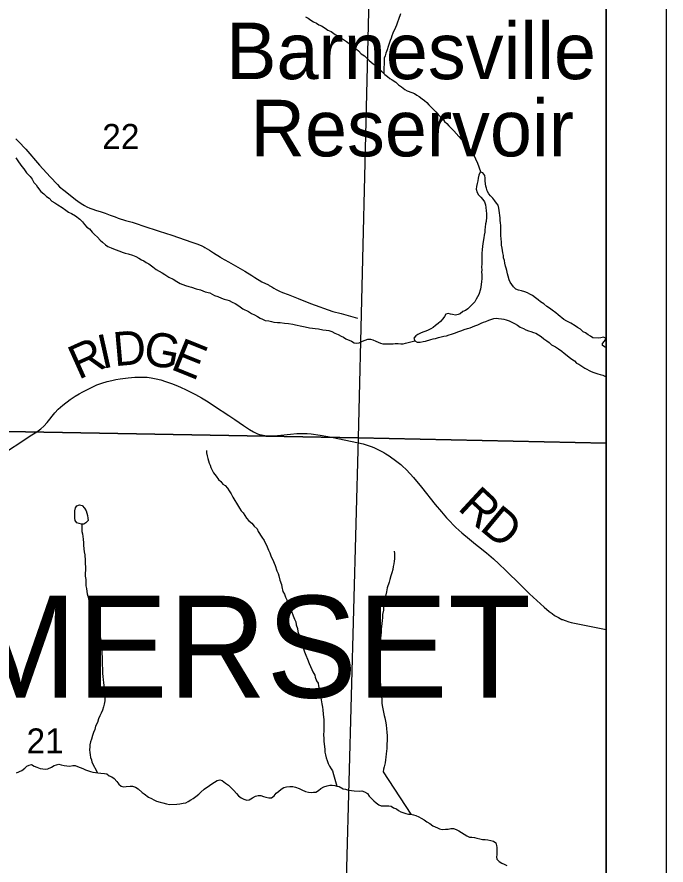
# Model space of a CAD drawing. Extents: x 0 to 34, y 0 to 22.
# Drawn here: x 29.33 to 30.417, y 16.803 to 18.224 of the extents above; entities that cross this region are included whole.
import ezdxf

# ---------------------------------------------------------------- set-up
doc = ezdxf.new("R2010")
doc.units = 0
for name, color, linetype in [('GM_X_Corporation', 7, 'Continuous'), ('GM_X_County_Road', 7, 'Continuous'), ('GM_X_County_Road_Text', 7, 'Continuous'), ('GM_X_Major_Lake', 7, 'Continuous'), ('GM_X_Major_Lake_Text', 7, 'Continuous'), ('GM_X_Minor_River', 7, 'Continuous'), ('GM_X_Section_Text', 7, 'Continuous'), ('GM_X_Township_Road', 7, 'Continuous'), ('GM_X_Township_Text', 7, 'Continuous'), ('SH_Data', 7, 'Continuous')]:
    doc.layers.add(name, color=color, linetype=linetype)

msp = doc.modelspace()

# ---------------------------------------------------------------- linework, layer by layer
at = {"layer": 'GM_X_Corporation'}
for points in [[(27.8031, 14.5091), (28.4032, 14.497), (28.7853, 14.4893), (29.1713, 14.4832), (29.2367, 14.4822), (30.3098, 14.464), (30.3167, 14.4639), (30.3167, 20.9), (27.1022, 20.9)], [(27.8031, 14.5091), (28.4032, 14.497), (28.7853, 14.4893), (29.1713, 14.4832), (29.2367, 14.4822), (30.3098, 14.464), (30.3167, 14.4639), (30.3167, 20.3649), (29.5503, 20.3788), (27.6751, 20.4106)]]:
    msp.add_lwpolyline(points, dxfattribs=at)
for points in [[(29.9261, 18.5329), (29.9011, 17.5188), (28.8799, 17.5369), (28.8973, 18.5532)], [(30.3167, 17.5099), (30.3167, 18.5238), (29.9261, 18.5329), (29.9011, 17.5188)], [(28.8799, 17.5369), (29.9011, 17.5188), (29.8741, 16.51), (28.863, 16.5324)], [(30.3167, 16.4991), (30.3167, 17.5099), (29.9011, 17.5188), (29.8741, 16.51)]]:
    msp.add_lwpolyline(points, close=True, dxfattribs=at)
at = {"layer": 'GM_X_County_Road'}
msp.add_lwpolyline([(29.3159, 17.4978), (29.3365, 17.5113), (29.3525, 17.522), (29.3634, 17.5289), (29.37, 17.5337), (29.3749, 17.538), (29.3805, 17.5445), (29.3934, 17.5604), (29.3991, 17.5669), (29.4071, 17.5736), (29.4192, 17.5826), (29.4259, 17.5871), (29.4276, 17.5883), (29.4341, 17.5922), (29.4406, 17.5959), (29.4449, 17.5981), (29.4573, 17.6041), (29.4641, 17.6072), (29.4724, 17.6103), (29.4814, 17.613), (29.4892, 17.6149), (29.4954, 17.6162), (29.5029, 17.6175), (29.5161, 17.6193), (29.5272, 17.6201), (29.5366, 17.6205), (29.5428, 17.6204), (29.5482, 17.6201), (29.555, 17.6194), (29.5633, 17.6177), (29.571, 17.6157), (29.5789, 17.6132), (29.5887, 17.6097), (29.5962, 17.6069), (29.6037, 17.6037), (29.6135, 17.5992), (29.6214, 17.5952), (29.6288, 17.5913), (29.6388, 17.5855), (29.6501, 17.5788), (29.6611, 17.5719), (29.6847, 17.5563), (29.695, 17.5492), (29.7093, 17.5393), (29.7194, 17.5326), (29.7263, 17.5285), (29.7294, 17.5271), (29.733, 17.5256), (29.7363, 17.5244), (29.7396, 17.5236), (29.7451, 17.5225), (29.7498, 17.522), (29.7547, 17.5219), (29.7602, 17.5221), (29.7664, 17.5226), (29.7879, 17.525), (29.7989, 17.5259), (29.8042, 17.526), (29.8159, 17.5257), (29.8229, 17.5252), (29.8375, 17.523), (29.8503, 17.5207), (29.8565, 17.5196), (29.8912, 17.5127), (29.9099, 17.5083), (29.9178, 17.5059), (29.9232, 17.504), (29.9276, 17.5022), (29.9351, 17.4988), (29.9442, 17.494), (29.9479, 17.4918), (29.9532, 17.4883), (29.9662, 17.4791), (29.9726, 17.4741), (29.9757, 17.4714), (29.9818, 17.4658), (29.9885, 17.4586), (29.9938, 17.4524), (30.0071, 17.4361), (30.0304, 17.4071), (30.0408, 17.3944), (30.0491, 17.3848), (30.0546, 17.3789), (30.0609, 17.3724), (30.0647, 17.3687), (30.0751, 17.3594), (30.0877, 17.3487), (30.0978, 17.3406), (30.1026, 17.3368), (30.116, 17.3259), (30.1279, 17.3157), (30.1368, 17.3077), (30.1486, 17.2965), (30.1733, 17.2722), (30.1883, 17.2572), (30.2126, 17.2351), (30.2211, 17.228), (30.2259, 17.2242), (30.2302, 17.2213), (30.2366, 17.2175), (30.2425, 17.2146), (30.2435, 17.2142), (30.2481, 17.2124), (30.2538, 17.2106), (30.2576, 17.2095), (30.2634, 17.2082), (30.3167, 17.1977)], dxfattribs=at)
at = {"layer": 'GM_X_Major_Lake'}
for points in [[(30.3167, 17.6695), (30.3147, 17.6706), (30.3101, 17.6731), (30.3104, 17.6769), (30.3138, 17.6808), (30.3164, 17.685), (30.3118, 17.6872), (30.3073, 17.686), (30.3035, 17.6855), (30.2944, 17.6861), (30.2902, 17.6887), (30.2864, 17.6909), (30.2817, 17.6946), (30.2779, 17.6964), (30.2733, 17.7005), (30.2687, 17.7035), (30.2645, 17.7064), (30.2572, 17.7109), (30.2504, 17.7142), (30.2458, 17.7171), (30.2362, 17.7245), (30.2324, 17.7279), (30.2258, 17.7323), (30.2216, 17.7356), (30.217, 17.7386), (30.212, 17.743), (30.2067, 17.7464), (30.2025, 17.7497), (30.1979, 17.7534), (30.1929, 17.7571), (30.1887, 17.7593), (30.1848, 17.7615), (30.1803, 17.763), (30.175, 17.7648), (30.1696, 17.7662), (30.1651, 17.7676), (30.1616, 17.7717), (30.1585, 17.7755), (30.1558, 17.7792), (30.1542, 17.7833), (30.1526, 17.7894), (30.1514, 17.7935), (30.1501, 17.7988), (30.1489, 17.8026), (30.1481, 17.8064), (30.1469, 17.8113), (30.1461, 17.8158), (30.1448, 17.8203), (30.1444, 17.8241), (30.1436, 17.8287), (30.1427, 17.8324), (30.1423, 17.8366), (30.1415, 17.8415), (30.141, 17.8464), (30.1405, 17.8521), (30.1404, 17.8574), (30.1399, 17.8631), (30.1399, 17.8677), (30.1401, 17.8745), (30.1397, 17.8786), (30.1392, 17.8824), (30.1388, 17.887), (30.1374, 17.8995), (30.1366, 17.9036), (30.1354, 17.9081), (30.133, 17.9119), (30.1303, 17.9156), (30.1265, 17.9201), (30.123, 17.9239), (30.1199, 17.9276), (30.1172, 17.9321), (30.116, 17.9366), (30.1148, 17.9404), (30.1143, 17.9442), (30.1138, 17.9491), (30.1138, 17.9536), (30.1133, 17.9582), (30.1098, 17.9627), (30.1053, 17.9634), (30.1035, 17.9588), (30.1024, 17.9538), (30.1017, 17.9493), (30.1007, 17.9447), (30.0996, 17.9397), (30.0989, 17.9352), (30.1006, 17.9295), (30.1029, 17.9254), (30.1067, 17.922), (30.1098, 17.9179), (30.1126, 17.9138)], [(30.1126, 17.9138), (30.1142, 17.9089), (30.115, 17.9044), (30.1155, 17.8991), (30.1159, 17.8945), (30.116, 17.8881), (30.1154, 17.8812), (30.1147, 17.8771), (30.1141, 17.8717), (30.1134, 17.8668), (30.1131, 17.863), (30.1124, 17.8581), (30.1117, 17.8535), (30.1107, 17.8474), (30.1097, 17.8398), (30.109, 17.8334), (30.1084, 17.8277), (30.1081, 17.8235), (30.1083, 17.8098), (30.108, 17.8045), (30.1081, 17.8), (30.1078, 17.7962), (30.1082, 17.7924), (30.1084, 17.7848), (30.1077, 17.7803), (30.1074, 17.7757), (30.1067, 17.7715), (30.106, 17.7677), (30.1032, 17.7586), (30.101, 17.7547), (30.0991, 17.7509), (30.0966, 17.7467), (30.0932, 17.7428), (30.0895, 17.739), (30.085, 17.7347), (30.0809, 17.732), (30.0768, 17.73), (30.0723, 17.7265), (30.0686, 17.725), (30.064, 17.7241), (30.0595, 17.7252), (30.0557, 17.7259), (30.0519, 17.7269), (30.0481, 17.7257), (30.0459, 17.7219), (30.0433, 17.7181), (30.0392, 17.7134), (30.0351, 17.7103), (30.0307, 17.7068), (30.0266, 17.7034), (30.0228, 17.701), (30.0183, 17.6987), (30.0146, 17.6971), (30.0097, 17.6955), (30.0059, 17.6939), (30.0014, 17.6919), (29.9977, 17.6896), (29.9947, 17.6857), (29.9959, 17.6812), (30.0001, 17.679), (30.005, 17.6787), (30.0099, 17.6799), (30.0141, 17.6808), (30.0227, 17.6836), (30.0269, 17.6844), (30.0307, 17.6852), (30.0359, 17.6865), (30.0401, 17.6877), (30.0446, 17.6889), (30.0491, 17.6897), (30.0536, 17.6913), (30.0578, 17.6925), (30.0623, 17.6941), (30.0698, 17.6965), (30.0747, 17.6985), (30.0788, 17.7001), (30.0841, 17.7017), (30.089, 17.7029), (30.0965, 17.7061), (30.1014, 17.7081), (30.107, 17.7109), (30.1112, 17.7124), (30.1149, 17.7136), (30.1198, 17.7156), (30.1285, 17.7184), (30.1322, 17.7189), (30.1364, 17.7186), (30.141, 17.7179), (30.1451, 17.7176), (30.1493, 17.7165), (30.1543, 17.7147), (30.1585, 17.7125), (30.163, 17.7103), (30.168, 17.7074), (30.1726, 17.7041), (30.1779, 17.7015), (30.1818, 17.6993), (30.1863, 17.6979), (30.1901, 17.6968), (30.1947, 17.6953), (30.1985, 17.6939)], [(30.1985, 17.6939), (30.2031, 17.6913), (30.2077, 17.6884), (30.2123, 17.6847), (30.2173, 17.681), (30.2211, 17.6784), (30.225, 17.6746), (30.2315, 17.671), (30.2364, 17.6676), (30.2422, 17.6636), (30.2464, 17.6602), (30.251, 17.6565), (30.2548, 17.6539), (30.2591, 17.6506), (30.2633, 17.6477), (30.2667, 17.6439), (30.2706, 17.6421), (30.2809, 17.6354), (30.2916, 17.63), (30.2958, 17.6281), (30.3026, 17.626), (30.3064, 17.6249), (30.311, 17.6235), (30.3152, 17.6213), (30.3167, 17.6201)]]:
    msp.add_lwpolyline(points, dxfattribs=at)
at = {"layer": 'GM_X_Minor_River'}
for points in [[(29.9724, 18.2287), (29.9687, 18.2196), (29.9673, 18.2146), (29.9655, 18.21), (29.9637, 18.2058), (29.9593, 18.1966), (29.9575, 18.1921), (29.9564, 18.1882), (29.955, 18.1844), (29.9539, 18.1806), (29.9517, 18.1741), (29.9499, 18.1684), (29.9478, 18.1631), (29.9467, 18.1585), (29.9449, 18.1543), (29.9444, 18.129)], [(29.8131, 18.224), (29.8177, 18.2214), (29.8223, 18.2185), (29.8265, 18.2155), (29.8315, 18.2133), (29.8353, 18.2104), (29.8399, 18.2086), (29.846, 18.2049), (29.8506, 18.2012), (29.8559, 18.199), (29.8628, 18.1942), (29.8701, 18.1901), (29.8766, 18.1861), (29.8816, 18.1824), (29.8923, 18.1746), (29.8965, 18.1716), (29.9019, 18.1668), (29.9062, 18.1619), (29.9119, 18.1583), (29.9161, 18.1545), (29.92, 18.1508), (29.9265, 18.1449), (29.9315, 18.1404), (29.9365, 18.1359), (29.9407, 18.1322), (29.9461, 18.1274), (29.9507, 18.1241), (29.9546, 18.1207), (29.9584, 18.1181), (29.9641, 18.1141), (29.9688, 18.11), (29.9741, 18.1063), (29.9795, 18.1022), (29.9833, 18.1), (29.9909, 18.0971), (29.9955, 18.0953), (29.9997, 18.0927), (30.0035, 18.0901), (30.0085, 18.0864), (30.0124, 18.0834), (30.0162, 18.0801), (30.0197, 18.0764), (30.0235, 18.0726), (30.0278, 18.0678), (30.0316, 18.0648), (30.0351, 18.0603), (30.0386, 18.0566), (30.0428, 18.0529), (30.0459, 18.0484), (30.0497, 18.045), (30.0532, 18.0413), (30.0571, 18.0376), (30.0613, 18.0331), (30.0698, 18.0234), (30.074, 18.0189), (30.079, 18.0133), (30.0825, 18.0085), (30.0864, 18.0043), (30.0895, 18.0002), (30.0926, 17.9957), (30.0949, 17.9916), (30.0969, 17.9879), (30.0981, 17.9841), (30.1004, 17.9803), (30.1067, 17.9631)], [(29.328, 17.9874), (29.333, 17.9811), (29.3385, 17.9732), (29.3419, 17.9691), (29.3462, 17.9624), (29.352, 17.9564), (29.3555, 17.9519), (29.3586, 17.9463), (29.3621, 17.9422), (29.3648, 17.9384), (29.3702, 17.9313), (29.3752, 17.9276), (29.3795, 17.9231), (29.384, 17.9202), (29.3887, 17.9153), (29.3936, 17.9124), (29.3986, 17.9091), (29.4059, 17.9043), (29.412, 17.8998), (29.4166, 17.8969), (29.4216, 17.8943), (29.4281, 17.8906), (29.4354, 17.8847), (29.44, 17.8806), (29.4431, 17.8761), (29.4469, 17.8716), (29.4515, 17.8687), (29.4562, 17.8634), (29.46, 17.859), (29.465, 17.8545), (29.4696, 17.85), (29.4731, 17.8463), (29.4781, 17.8418), (29.4823, 17.8389), (29.4877, 17.8367), (29.4945, 17.8342), (29.5021, 17.8313), (29.506, 17.8294), (29.5113, 17.828), (29.5162, 17.827), (29.5238, 17.8248), (29.5292, 17.8223), (29.5341, 17.8197), (29.5387, 17.8168), (29.5425, 17.8149), (29.5467, 17.8124), (29.5509, 17.8102), (29.5575, 17.805), (29.5632, 17.8005), (29.5682, 17.798), (29.5732, 17.795), (29.5777, 17.7924), (29.5842, 17.788), (29.5915, 17.7843)], [(29.5915, 17.7843), (29.598, 17.7803), (29.6034, 17.7773), (29.6125, 17.7737), (29.6178, 17.7723), (29.6224, 17.7712), (29.6304, 17.7683), (29.6372, 17.7666), (29.6452, 17.7629), (29.6528, 17.7615), (29.6608, 17.7571), (29.6665, 17.7553), (29.6726, 17.7528), (29.6768, 17.751), (29.6814, 17.7495), (29.6852, 17.7485), (29.6906, 17.7459), (29.6955, 17.7437), (29.7016, 17.74), (29.7082, 17.7348), (29.7177, 17.7305), (29.7227, 17.7271), (29.7276, 17.7246), (29.733, 17.7216), (29.7372, 17.7191), (29.741, 17.7172), (29.7456, 17.7154), (29.7516, 17.7144), (29.7562, 17.7133), (29.76, 17.7126), (29.7661, 17.712), (29.771, 17.7117), (29.7782, 17.7107), (29.7846, 17.7101), (29.7918, 17.709), (29.7964, 17.708), (29.807, 17.7059), (29.8124, 17.7045), (29.8196, 17.7031), (29.8249, 17.7024), (29.8294, 17.7017), (29.8351, 17.7011), (29.8423, 17.6997), (29.8476, 17.699), (29.8522, 17.6984), (29.8571, 17.6969), (29.8625, 17.694), (29.8678, 17.6918), (29.8728, 17.6889), (29.8766, 17.687), (29.8808, 17.6845), (29.89, 17.6805), (29.8946, 17.6779), (29.8987, 17.6772), (29.9029, 17.6777), (29.9085, 17.6804), (29.913, 17.6824), (29.9175, 17.684), (29.9221, 17.6841), (29.9259, 17.683), (29.9308, 17.6808), (29.9347, 17.6786), (29.9388, 17.6772), (29.9426, 17.6761), (29.9464, 17.6758), (29.9502, 17.6762), (29.9555, 17.6763), (29.9597, 17.676), (29.9634, 17.6765), (29.968, 17.6765), (29.9729, 17.6762), (29.9767, 17.6763), (29.9805, 17.6771), (29.9959, 17.6812)], [(29.6472, 17.4975), (29.6477, 17.4934), (29.6485, 17.4885), (29.6497, 17.4839), (29.6509, 17.4802), (29.6517, 17.4764), (29.6533, 17.4726), (29.6545, 17.4689), (29.6592, 17.4598), (29.6635, 17.4542), (29.6677, 17.449), (29.6716, 17.4457), (29.675, 17.4412), (29.6789, 17.4386), (29.6827, 17.4345), (29.6855, 17.4296), (29.6886, 17.4247), (29.6917, 17.4195), (29.6948, 17.4135), (29.6979, 17.409), (29.7026, 17.4007), (29.7057, 17.3966), (29.7088, 17.3929), (29.7115, 17.3884), (29.7143, 17.3842), (29.7181, 17.3798), (29.7231, 17.3757), (29.7274, 17.3708), (29.732, 17.366), (29.7339, 17.3615), (29.7398, 17.3521), (29.744, 17.3469), (29.7491, 17.3363), (29.7511, 17.3307), (29.7535, 17.3262), (29.7559, 17.3194), (29.7586, 17.3141), (29.7606, 17.3085), (29.7626, 17.3047), (29.7654, 17.2957), (29.7673, 17.2915), (29.7685, 17.2874), (29.7702, 17.2802), (29.7729, 17.2731), (29.7734, 17.2693), (29.7754, 17.261), (29.7778, 17.2565), (29.7798, 17.2516), (29.7821, 17.2471), (29.7841, 17.241), (29.7865, 17.2346), (29.79, 17.2283), (29.7924, 17.2207), (29.7948, 17.2147), (29.7967, 17.2102), (29.7976, 17.2053), (29.7996, 17.1992), (29.8004, 17.1943), (29.8024, 17.1875), (29.8033, 17.1811), (29.8061, 17.1751), (29.8077, 17.1702), (29.81, 17.1653), (29.8116, 17.1604), (29.8136, 17.1548), (29.8164, 17.148), (29.8191, 17.1404), (29.8239, 17.1307), (29.8254, 17.1265), (29.8286, 17.1213), (29.8294, 17.1175), (29.8318, 17.1115), (29.8341, 17.1077), (29.8349, 17.1032), (29.8362, 17.0975), (29.8375, 17.0881), (29.8387, 17.0832), (29.8407, 17.073), (29.8416, 17.0677), (29.8421, 17.0631), (29.8429, 17.056), (29.8434, 17.0507), (29.8439, 17.0469), (29.844, 17.0393), (29.8441, 17.0336), (29.8438, 17.0272), (29.8435, 17.0218), (29.844, 17.0143), (29.8441, 17.0101), (29.8455, 16.9972), (29.8456, 16.9923), (29.8464, 16.9874), (29.848, 16.9825), (29.8492, 16.9783), (29.8512, 16.9731), (29.8535, 16.9686), (29.8559, 16.9644), (29.8582, 16.9607), (29.8598, 16.9547), (29.8658, 16.9354)], [(29.4382, 17.374), (29.4302, 17.3761), (29.4275, 17.3799), (29.4271, 17.384), (29.4269, 17.3928), (29.4272, 17.3965), (29.4283, 17.4011), (29.4305, 17.4049), (29.435, 17.4065), (29.4392, 17.4055), (29.443, 17.401), (29.4458, 17.3965), (29.4473, 17.3924), (29.4485, 17.3886), (29.449, 17.384), (29.4495, 17.3803), (29.4457, 17.376), (29.442, 17.3741), (29.4382, 17.374)], [(29.4386, 17.374), (29.4388, 17.3619), (29.4396, 17.3577), (29.4405, 17.3532), (29.4409, 17.349), (29.4414, 17.343), (29.4418, 17.3388), (29.4423, 17.3327), (29.4424, 17.3278), (29.4436, 17.3225), (29.4446, 17.3134), (29.4449, 17.2968), (29.4446, 17.2918), (29.4446, 17.2869), (29.4455, 17.2816), (29.4452, 17.2763), (29.4457, 17.271), (29.4465, 17.2665), (29.447, 17.2615), (29.4478, 17.2574), (29.449, 17.2536), (29.4498, 17.2491), (29.4514, 17.2446), (29.4539, 17.2348), (29.4551, 17.2302), (29.4563, 17.2261), (29.4575, 17.2212), (29.4595, 17.2155), (29.4615, 17.2106), (29.4627, 17.2065), (29.4647, 17.202), (29.467, 17.1967), (29.4682, 17.1918), (29.4687, 17.188), (29.4707, 17.1797), (29.4716, 17.1752), (29.4725, 17.1619), (29.4728, 17.1468), (29.4729, 17.1396), (29.4731, 17.1308), (29.4736, 17.1244), (29.4737, 17.1183), (29.4745, 17.1138), (29.475, 17.1085), (29.4754, 17.1043), (29.4763, 17.0975), (29.4772, 17.0919), (29.4773, 17.0831), (29.477, 17.0782), (29.4764, 17.0725), (29.4749, 17.0679), (29.4731, 17.0622), (29.471, 17.0573), (29.4688, 17.053), (29.4666, 17.0481), (29.4648, 17.0416), (29.4619, 17.0355), (29.4605, 17.0301), (29.4583, 17.0248), (29.4565, 17.0202), (29.4551, 17.0137), (29.4533, 17.0092), (29.4522, 17.0046), (29.4519, 17.0008), (29.4516, 16.9959), (29.452, 16.9917), (29.4525, 16.9879), (29.4533, 16.9834), (29.4549, 16.9792), (29.4557, 16.9755), (29.4648, 16.9576)], [(29.9616, 17.3288), (29.962, 17.325), (29.9622, 17.3159), (29.9618, 17.3121), (29.9612, 17.3075), (29.9601, 17.3029), (29.9591, 17.298), (29.9576, 17.2927), (29.9558, 17.2877), (29.9544, 17.2816), (29.953, 17.277), (29.9501, 17.2671), (29.9487, 17.2607), (29.947, 17.2534), (29.9459, 17.2492), (29.9456, 17.2454), (29.9446, 17.2401), (29.9439, 17.2356), (29.9436, 17.2302), (29.9422, 17.2226), (29.9419, 17.2169), (29.9413, 17.2124), (29.941, 17.2074), (29.9403, 17.2025), (29.94, 17.198), (29.9397, 17.1926), (29.939, 17.1885), (29.9387, 17.1824), (29.9381, 17.1771), (29.9378, 17.1725), (29.9375, 17.1668), (29.937, 17.1528), (29.9374, 17.1482), (29.9369, 17.1365), (29.9373, 17.1327), (29.9376, 17.1194), (29.938, 17.1149), (29.9381, 17.1107), (29.9386, 17.105), (29.9395, 17.096), (29.9399, 17.0922), (29.9404, 17.0865), (29.9409, 17.0793), (29.941, 17.0744), (29.9414, 17.0702), (29.9427, 17.0649), (29.9435, 17.0589), (29.9451, 17.0536), (29.946, 17.0498), (29.9476, 17.0415), (29.9481, 17.0374), (29.9489, 17.0317), (29.9494, 17.0249), (29.9499, 17.02), (29.95, 17.0135), (29.9494, 17.004), (29.9491, 16.998), (29.9485, 16.9938), (29.9482, 16.9892), (29.9479, 16.9839), (29.9472, 16.979), (29.9465, 16.9744), (29.9447, 16.9675), (29.9437, 16.9637), (29.943, 16.9592), (29.9893, 16.888)], [(29.3293, 16.9573), (29.3383, 16.9612), (29.3431, 16.9655), (29.3469, 16.9686), (29.3506, 16.9706), (29.3544, 16.9714), (29.359, 16.9688), (29.3632, 16.967), (29.3689, 16.9648), (29.3734, 16.9641), (29.378, 16.9638), (29.3821, 16.9643), (29.3878, 16.967), (29.3923, 16.9698), (29.3964, 16.971), (29.4005, 16.9718), (29.4043, 16.9711), (29.4093, 16.9697), (29.4135, 16.969), (29.4184, 16.9687), (29.4237, 16.9696), (29.4278, 16.9697), (29.4316, 16.9682), (29.4358, 16.9664), (29.4404, 16.9646), (29.445, 16.9624), (29.4534, 16.9595), (29.4572, 16.9588), (29.4617, 16.9581), (29.4655, 16.9574), (29.4704, 16.9572), (29.4769, 16.9565), (29.4807, 16.9558), (29.4845, 16.9525), (29.4891, 16.9507), (29.4929, 16.9481), (29.4972, 16.9428), (29.5006, 16.9387), (29.5045, 16.9354)], [(29.5045, 16.9354), (29.5087, 16.9343), (29.5128, 16.9344), (29.5196, 16.9349), (29.5238, 16.935), (29.5287, 16.9336), (29.5333, 16.9306), (29.5395, 16.9247), (29.5433, 16.9224), (29.5506, 16.9169), (29.5555, 16.9147), (29.5594, 16.9121), (29.5636, 16.9103), (29.5697, 16.9085), (29.5742, 16.9071), (29.5803, 16.9053), (29.5856, 16.9046), (29.5977, 16.9048), (29.6026, 16.9053), (29.6083, 16.9066), (29.6128, 16.9074), (29.6169, 16.9094), (29.621, 16.9121), (29.6252, 16.9144), (29.6297, 16.9176), (29.6345, 16.9218), (29.6382, 16.9249), (29.6438, 16.9299), (29.6524, 16.9362), (29.6561, 16.9393), (29.661, 16.9416), (29.6655, 16.9444), (29.6697, 16.9456), (29.6735, 16.9449), (29.6792, 16.9404), (29.6842, 16.9367), (29.6934, 16.9278), (29.6977, 16.9229), (29.7011, 16.9192), (29.7057, 16.9159), (29.7099, 16.9133), (29.7149, 16.9119), (29.719, 16.9123), (29.7247, 16.9155), (29.7292, 16.9186), (29.7341, 16.9198), (29.7386, 16.9195), (29.7428, 16.9181), (29.747, 16.917), (29.7519, 16.9156), (29.7561, 16.9156), (29.7606, 16.9188), (29.7643, 16.9234), (29.768, 16.9261), (29.7725, 16.93), (29.777, 16.9327), (29.7811, 16.9339), (29.7872, 16.9344), (29.7921, 16.9345), (29.7966, 16.9334), (29.8027, 16.9313), (29.8073, 16.9291), (29.813, 16.9265), (29.818, 16.9251), (29.8229, 16.9248), (29.8267, 16.9249), (29.8304, 16.9253), (29.8349, 16.9277), (29.8387, 16.9312), (29.8439, 16.9339), (29.8492, 16.9359), (29.8537, 16.9367), (29.8579, 16.9368), (29.862, 16.9361), (29.8658, 16.9354), (29.8696, 16.9344), (29.8761, 16.9307), (29.8799, 16.93), (29.8853, 16.9286), (29.8902, 16.9279), (29.8944, 16.9276), (29.9034, 16.927), (29.9076, 16.9271), (29.9118, 16.9256), (29.9171, 16.9227), (29.9199, 16.9186), (29.9276, 16.9104), (29.9314, 16.907), (29.936, 16.9041), (29.9398, 16.9023), (29.9444, 16.902), (29.9527, 16.9021), (29.9565, 16.9018), (29.9603, 16.8988), (29.9653, 16.897), (29.9691, 16.8944), (29.9729, 16.8919), (29.9775, 16.8904), (29.9813, 16.8893), (29.9855, 16.8883), (29.9893, 16.888)], [(29.9893, 16.888), (29.9938, 16.8873), (29.998, 16.8859), (30.003, 16.884), (30.0068, 16.8815), (30.0118, 16.8785), (30.0164, 16.8752), (30.0213, 16.8726), (30.0263, 16.8689), (30.0339, 16.8653), (30.0377, 16.8638), (30.0419, 16.8628), (30.0476, 16.8629), (30.0521, 16.8633), (30.0567, 16.8642), (30.0608, 16.8642), (30.0654, 16.8624), (30.07, 16.8602), (30.0742, 16.8576), (30.083, 16.8517), (30.0879, 16.8499), (30.0917, 16.8496), (30.0963, 16.8493), (30.1001, 16.8479), (30.105, 16.8472), (30.1092, 16.8461), (30.1137, 16.8458), (30.1183, 16.8452), (30.1232, 16.8441), (30.1278, 16.8431), (30.1316, 16.8401), (30.1328, 16.8359), (30.1336, 16.8322), (30.1337, 16.8269), (30.1335, 16.8204), (30.1328, 16.8166), (30.1336, 16.8128), (30.1375, 16.8087), (30.1417, 16.8062), (30.1459, 16.8043), (30.1504, 16.8021)]]:
    msp.add_lwpolyline(points, dxfattribs=at)
at = {"layer": 'GM_X_Township_Road'}
msp.add_lwpolyline([(29.328, 18.0194), (29.3326, 18.015), (29.3451, 18.0019), (29.368, 17.9754), (29.386, 17.9556), (29.3979, 17.9431), (29.4016, 17.9393), (29.4086, 17.9333), (29.4162, 17.9273), (29.4279, 17.9181), (29.4322, 17.9149), (29.4376, 17.9113), (29.4433, 17.9079), (29.4472, 17.9058), (29.4522, 17.9035), (29.4569, 17.9016), (29.4615, 17.9), (29.4709, 17.897), (29.4779, 17.8948), (29.4862, 17.8917), (29.4944, 17.8886), (29.4997, 17.8867), (29.512, 17.8827), (29.5232, 17.8796), (29.5311, 17.8773), (29.5409, 17.874), (29.568, 17.865), (29.5893, 17.8583), (29.6229, 17.8465), (29.6329, 17.8428), (29.6396, 17.84), (29.643, 17.8384), (29.6445, 17.8376), (29.6524, 17.8329), (29.6594, 17.8283), (29.6706, 17.8213), (29.6721, 17.8204), (29.6843, 17.8132), (29.7118, 17.7977), (29.7233, 17.7907), (29.7283, 17.7872), (29.7285, 17.7871), (29.7403, 17.7801), (29.751, 17.7747), (29.7522, 17.774), (29.7555, 17.7722), (29.7569, 17.7713), (29.7602, 17.7691), (29.764, 17.767), (29.7697, 17.7641), (29.7746, 17.762), (29.7839, 17.7587), (29.8007, 17.7519), (29.8218, 17.7438), (29.8589, 17.7304), (29.873, 17.7269), (29.8886, 17.7224), (29.9004, 17.7193)], dxfattribs=at)
at = {"layer": 'SH_Data'}
for points in [[(23.4167, 21), (30.4167, 21), (30.4167, 14), (23.4167, 14)], [(23.5167, 20.9), (30.3167, 20.9), (30.3167, 14.1), (23.5167, 14.1)]]:
    msp.add_lwpolyline(points, close=True, dxfattribs=at)

# ---------------------------------------------------------------- texts
at = {"layer": 'GM_X_County_Road_Text'}
for s, rotation, p in [('I', 12.6313, (29.4728, 17.6337)), ('D', 5.0153, (29.4936, 17.6385)), ('G', 349.0841, (29.5392, 17.6431)), ('R', 24.1434, (29.4331, 17.6155)), ('E', 337.9897, (29.5856, 17.6344)), ('R', 317.2388, (30.0662, 17.3996)), ('D', 320.3013, (30.1029, 17.3657))]:
    msp.add_text(s, height=0.0568, rotation=rotation, dxfattribs=at).set_placement(p)
at = {"layer": 'GM_X_Major_Lake_Text'}
for s, height, rotation, p in [('Barnesville', 0.094695, 0.0039, (29.6801, 18.1194)), ('Reservoir', 0.09469, 0.0045, (29.7208, 17.9901))]:
    msp.add_text(s, height=height, rotation=rotation, dxfattribs=at).set_placement(p)
at = {"layer": 'GM_X_Section_Text'}
for s, p in [('22', (29.4729, 18.0025)), ('21', (29.3462, 16.99))]:
    msp.add_text(s, height=0.04186, rotation=0, dxfattribs=at).set_placement(p)
at = {"layer": 'GM_X_Township_Text'}
msp.add_text('SOMERSET', height=0.17045, rotation=0, dxfattribs=at).set_placement((28.9118, 17.0836))

doc.saveas('drawing.dxf')
